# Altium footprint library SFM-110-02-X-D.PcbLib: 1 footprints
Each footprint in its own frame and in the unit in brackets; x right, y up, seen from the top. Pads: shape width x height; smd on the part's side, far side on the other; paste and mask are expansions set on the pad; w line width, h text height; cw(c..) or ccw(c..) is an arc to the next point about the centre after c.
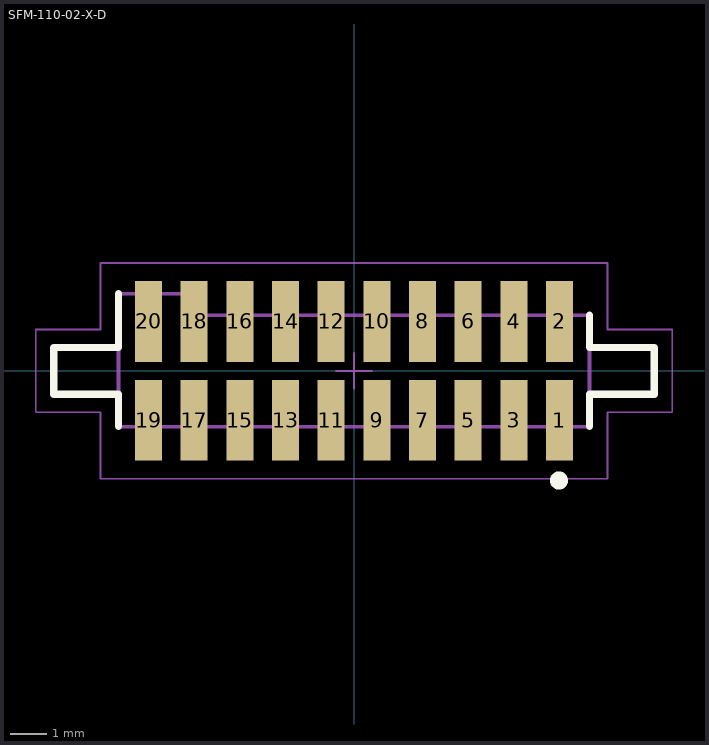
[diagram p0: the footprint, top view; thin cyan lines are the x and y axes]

## SFM-110-02-X-D [mm] "1.27mm pitch, 20 pin, socket strip; SMT"
height 4.57
pads (20):
  rect 0.75x2.25 smd mask+0: 1(5.715,-1.375) 2(5.715,1.375) 3(4.445,-1.375) 4(4.445,1.375) 5(3.175,-1.375) 6(3.175,1.375) 7(1.905,-1.375) 8(1.905,1.375) 9(0.635,-1.375) 10(0.635,1.375) 11(-0.635,-1.375) 12(-0.635,1.375) 13(-1.905,-1.375) 14(-1.905,1.375) 15(-3.175,-1.375) 16(-3.175,1.375) 17(-4.445,-1.375) 18(-4.445,1.375) 19(-5.715,-1.375) 20(-5.715,1.375)
Top Overlay:
  circle w0.25: c5.7,-3.05 r0.125
  lines w0.2: -6.55,-1.55 -6.55,-0.65 -8.35,-0.65 -8.35,0.65 -6.55,0.65 -6.55,2.15 ; 6.55,-1.55 6.55,-0.65 8.35,-0.65 8.35,0.65 6.55,0.65 6.55,1.55
Mechanical 12:
  lines w0.001: -8.35,-0.65 -8.35,0.65 -6.55,0.65 -6.55,2.15 -4.5,2.15 -4.5,1.55 6.55,1.55 6.55,0.65 8.35,0.65 8.35,-0.65 6.55,-0.65 6.55,-1.55 -6.55,-1.55 -6.55,-0.65 -8.35,-0.65
Mechanical 13:
  lines w0.1: -6.55,-0.65 -8.35,-0.65 -8.35,0.65 -6.55,0.65 ; -6.55,-0.65 -6.55,-1.55 6.55,-1.55 6.55,-0.65 ; -6.55,-0.65 -6.55,0.65 ; -6.55,0.65 -6.55,2.15 -4.5,2.15 -4.5,1.55 6.55,1.55 6.55,0.65 ; 6.55,-0.65 8.35,-0.65 8.35,0.65 6.55,0.65 ; 6.55,-0.65 6.55,0.65
  text ".Designator" at 0,-0.127 h1.52
Mechanical 15:
  lines w0.05: -0.5,0 0.5,0 ; 0,-0.5 0,0.5 ; -8.85,-1.15 -7.05,-1.15 -7.05,-3 7.05,-3 7.05,-1.15 8.85,-1.15 8.85,1.15 7.05,1.15 7.05,3 -7.05,3 -7.05,1.15 -8.85,1.15 -8.85,-1.15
